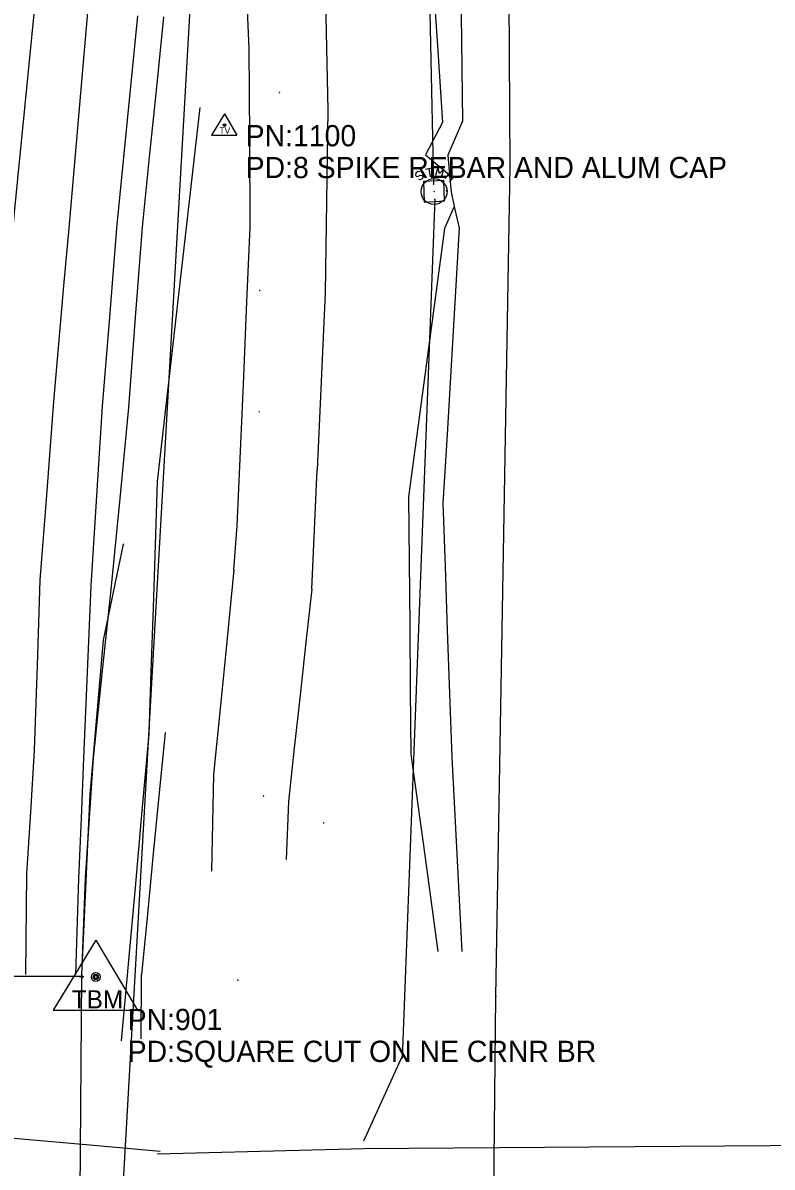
# Model space of a CAD drawing. Extents: x 1930288 to 1941089, y 588389 to 611475.
# Drawn here: x 1930874.5 to 1931050.9, y 598182.1 to 598451.6 of the extents above; entities that cross this region are included whole.
import ezdxf

# ---------------------------------------------------------------- set-up
doc = ezdxf.new("R2010")
doc.units = 0
for name, color, linetype in [('S_BASELINE', 7, 'Continuous'), ('S_BRIDGE', 7, 'Continuous'), ('S_DITCHLINE', 7, 'Continuous'), ('S_DROP_INLET', 7, 'Continuous'), ('S_EDGE_PAVEMENT', 7, 'Continuous'), ('S_GUARDRAIL', 7, 'Continuous'), ('S_MSC_PT_SYM', 7, 'Continuous'), ('S_PAVEMENT_CROWN', 7, 'Continuous'), ('S_PRIMARY_CTL', 7, 'Continuous'), ('S_PRIMARY_CTL_ANNOT', 7, 'Continuous'), ('S_RDW_PT_SYM', 7, 'Continuous'), ('S_SANITARY_SEWER', 7, 'Continuous'), ('S_SECONDARY_CTL', 7, 'Continuous'), ('S_SECONDARY_CTL_ANNOT', 7, 'Continuous'), ('S_SHOULDER', 7, 'Continuous'), ('S_STORM_SEWER', 7, 'Continuous'), ('S_STR_PT_SYM', 7, 'Continuous'), ('S_STREAM', 7, 'Continuous'), ('S_UTL_PT_SYM', 7, 'Continuous')]:
    doc.layers.add(name, color=color, linetype=linetype)

msp = doc.modelspace()

# ---------------------------------------------------------------- linework, layer by layer
at = {"layer": 'S_BASELINE'}
msp.add_line((1930894.27, 598110.49), (1930946.09, 599020.44), dxfattribs=at)
at = {"layer": 'S_BRIDGE'}
for p, q in [((1930888.36, 598226.99), (1930860.72, 598227)), ((1930887.7, 598136.81), (1930888.36, 598226.99))]:
    msp.add_line(p, q, dxfattribs=at)
at = {"layer": 'S_DITCHLINE'}
for points in [[(1930970.71, 598466.55), (1930972, 598447.33), (1930973.28, 598428.1), (1930969.3, 598420.53), (1930974.95, 598415.77), (1930975.3, 598411.84), (1930976.08, 598408.31), (1930973.77, 598403.14), (1930971.65, 598387.34), (1930969.52, 598371.55), (1930967.39, 598355.75), (1930965.27, 598339.95), (1930965.42, 598324.8), (1930965.57, 598309.65), (1930965.72, 598294.5), (1930965.87, 598279.35), (1930969.03, 598256.12), (1930972.19, 598232.9)], [(1930977.56, 598465.96), (1930977.77, 598447.19), (1930977.99, 598428.41), (1930974.55, 598420.45), (1930974.95, 598415.77)], [(1930916.13, 598431.64), (1930913.63, 598409.61), (1930911.14, 598387.59), (1930908.64, 598365.57), (1930906.15, 598343.55), (1930905.65, 598328.67), (1930905.16, 598313.8), (1930904.66, 598298.92), (1930904.17, 598284.05), (1930902.54, 598266), (1930900.92, 598247.96), (1930899.29, 598229.92), (1930897.66, 598211.87)], [(1930976.08, 598408.31), (1930977.25, 598403.25), (1930976.29, 598387.06), (1930975.33, 598370.87), (1930974.37, 598354.68), (1930973.41, 598338.49), (1930973.92, 598323.54), (1930974.43, 598308.59), (1930974.94, 598293.64), (1930975.46, 598278.69), (1930976.64, 598255.8), (1930977.83, 598232.91)], [(1930907.96, 598284.5), (1930906.57, 598270.24), (1930905.19, 598255.98), (1930903.81, 598241.71), (1930902.42, 598227.45)], [(1930902.33, 598212.31), (1930902.42, 598227.45)], [(1930963.83, 598208.28), (1930954.67, 598188.22)]]:
    msp.add_lwpolyline(points, dxfattribs=at)
at = {"layer": 'S_DROP_INLET'}
for points in [[(1930973.58, 598414.44), (1930968.84, 598414.2)], [(1930968.84, 598414.2), (1930969.01, 598409.36), (1930973.8, 598409.66), (1930973.58, 598414.44)]]:
    msp.add_lwpolyline(points, dxfattribs=at)
at = {"layer": 'S_EDGE_PAVEMENT'}
for points in [[(1930925.3, 598627.92), (1930936.56, 598622.51), (1930941.76, 598599.13), (1930942.55, 598578.56), (1930943.33, 598557.99), (1930943.76, 598537.25), (1930944.18, 598516.5), (1930944.75, 598495.82), (1930945.32, 598475.13), (1930945.82, 598453.1), (1930946.32, 598431.07), (1930946.01, 598409.55), (1930945.7, 598388.03), (1930944.74, 598367.17), (1930943.78, 598346.31)], [(1930924.96, 598333.18), (1930925.73, 598350.75), (1930926.49, 598368.33), (1930927.26, 598385.9), (1930928.03, 598403.47), (1930927.92, 598424.51), (1930927.81, 598445.55), (1930926.85, 598467.37), (1930925.9, 598489.18), (1930925.69, 598510.76), (1930925.47, 598532.34), (1930926.46, 598553.81), (1930927.46, 598575.27), (1930926.63, 598597.79), (1930922.74, 598599.04)], [(1930877.33, 598456.1), (1930875.68, 598439.46), (1930874.03, 598422.82), (1930872.39, 598406.18), (1930870.73, 598384.64), (1930869.07, 598363.1), (1930867.63, 598342.37), (1930866.18, 598321.65), (1930865.17, 598301.92), (1930864.16, 598282.2), (1930863.63, 598267.31), (1930863.11, 598252.42), (1930862.8, 598239.89), (1930862.49, 598227.37)], [(1930901.49, 598453.28), (1930899.84, 598436.61), (1930898.18, 598419.94), (1930896.52, 598403.28), (1930894.85, 598382.32), (1930893.18, 598361.36), (1930891.86, 598340.18), (1930890.53, 598319), (1930889.64, 598298.71), (1930888.76, 598278.42), (1930888.18, 598264.26), (1930887.6, 598250.1), (1930886.87, 598227.49)], [(1930942.49, 598318.25), (1930943.13, 598332.28), (1930943.78, 598346.31)], [(1930924.18, 598322.8), (1930924.96, 598333.18)], [(1930924.18, 598322.8), (1930921.77, 598298.69), (1930919.36, 598274.58), (1930918.9, 598251.78)], [(1930942.49, 598318.25), (1930941.13, 598305.75), (1930939.76, 598293.25), (1930938.4, 598280.75), (1930937.03, 598268.24), (1930936.52, 598254.54)]]:
    msp.add_lwpolyline(points, dxfattribs=at)
at = {"layer": 'S_GUARDRAIL'}
for p, q in [((1930893.46, 598306.18), (1930898.15, 598328.8)), ((1930890.3, 598269.99), (1930893.46, 598306.18)), ((1930888.4, 598227.43), (1930890.3, 598269.99))]:
    msp.add_line(p, q, dxfattribs=at)
at = {"layer": 'S_MSC_PT_SYM'}
for points in [[(1930934.89, 598435.22), (1930934.89, 598435.27), (1930934.89, 598435.22), (1930934.84, 598435.22), (1930934.89, 598435.22), (1930934.89, 598435.17), (1930934.89, 598435.22), (1930934.94, 598435.22)], [(1930971.17, 598413.62), (1930971.17, 598413.67), (1930971.17, 598413.62), (1930971.12, 598413.62), (1930971.17, 598413.62), (1930971.17, 598413.57), (1930971.17, 598413.62), (1930971.22, 598413.62)], [(1930974.21, 598412.06), (1930974.21, 598412.11), (1930974.21, 598412.06), (1930974.16, 598412.06), (1930974.21, 598412.06), (1930974.21, 598412.01), (1930974.21, 598412.06), (1930974.26, 598412.06)], [(1930971.47, 598410.05), (1930971.47, 598410.1), (1930971.47, 598410.05), (1930971.42, 598410.05), (1930971.47, 598410.05), (1930971.47, 598410), (1930971.47, 598410.05), (1930971.52, 598410.05)], [(1930930.25, 598388.53), (1930930.25, 598388.58), (1930930.25, 598388.53), (1930930.2, 598388.53), (1930930.25, 598388.53), (1930930.25, 598388.48), (1930930.25, 598388.53), (1930930.3, 598388.53)], [(1930930.16, 598360.03), (1930930.16, 598360.08), (1930930.16, 598360.03), (1930930.11, 598360.03), (1930930.16, 598360.03), (1930930.16, 598359.98), (1930930.16, 598360.03), (1930930.21, 598360.03)], [(1930931.15, 598269.52), (1930931.15, 598269.57), (1930931.15, 598269.52), (1930931.1, 598269.52), (1930931.15, 598269.52), (1930931.15, 598269.47), (1930931.15, 598269.52), (1930931.2, 598269.52)], [(1930945.33, 598263.18), (1930945.33, 598263.23), (1930945.33, 598263.18), (1930945.28, 598263.18), (1930945.33, 598263.18), (1930945.33, 598263.13), (1930945.33, 598263.18), (1930945.38, 598263.18)], [(1930925.1, 598226.15), (1930925.1, 598226.2), (1930925.1, 598226.15), (1930925.05, 598226.15), (1930925.1, 598226.15), (1930925.1, 598226.1), (1930925.1, 598226.15), (1930925.15, 598226.15)], [(1930933.25, 598209.13), (1930933.25, 598209.18), (1930933.25, 598209.13), (1930933.2, 598209.13), (1930933.25, 598209.13), (1930933.25, 598209.08), (1930933.25, 598209.13), (1930933.3, 598209.13)]]:
    msp.add_lwpolyline(points, dxfattribs=at)
at = {"layer": 'S_PAVEMENT_CROWN'}
msp.add_lwpolyline([(1930890.05, 598457.73), (1930888.86, 598444.11), (1930887.67, 598430.49), (1930886.47, 598416.87), (1930885.28, 598403.25), (1930884.09, 598389.63), (1930882.9, 598376.01), (1930881.71, 598362.39), (1930880.11, 598341.36), (1930878.51, 598320.33), (1930877.82, 598300.32), (1930877.13, 598280.3), (1930876.25, 598265.74), (1930875.37, 598251.17), (1930875.13, 598227.51)], dxfattribs=at)
at = {"layer": 'S_PRIMARY_CTL'}
for p, q in [((1930891.66, 598235.59), (1930881.63, 598219.07)), ((1930891.66, 598235.59), (1930901.49, 598219.07)), ((1930881.63, 598219.07), (1930901.49, 598219.07))]:
    msp.add_line(p, q, dxfattribs=at)
for radius in [1.04, 0.609, 0.344]:
    msp.add_circle((1930891.66, 598226.89), radius, dxfattribs=at)
at = {"layer": 'S_RDW_PT_SYM'}
for points in [[(1930898.15, 598328.8), (1930898.15, 598328.85), (1930898.15, 598328.8), (1930898.1, 598328.8), (1930898.15, 598328.8), (1930898.15, 598328.75), (1930898.15, 598328.8), (1930898.2, 598328.8)], [(1930893.46, 598306.18), (1930893.46, 598306.23), (1930893.46, 598306.18), (1930893.41, 598306.18), (1930893.46, 598306.18), (1930893.46, 598306.13), (1930893.46, 598306.18), (1930893.51, 598306.18)], [(1930890.3, 598269.99), (1930890.3, 598270.04), (1930890.3, 598269.99), (1930890.25, 598269.99), (1930890.3, 598269.99), (1930890.3, 598269.94), (1930890.3, 598269.99), (1930890.35, 598269.99)], [(1930888.4, 598227.43), (1930888.4, 598227.48), (1930888.4, 598227.43), (1930888.35, 598227.43), (1930888.4, 598227.43), (1930888.4, 598227.38), (1930888.4, 598227.43), (1930888.45, 598227.43)]]:
    msp.add_lwpolyline(points, dxfattribs=at)
at = {"layer": 'S_SANITARY_SEWER'}
for p, q in [((1930989.23, 598417.74), (1930987.94, 598658.53)), ((1930985.88, 598222.31), (1930989.23, 598417.74)), ((1930984.75, 598112), (1930985.88, 598222.31))]:
    msp.add_line(p, q, dxfattribs=at)
at = {"layer": 'S_SECONDARY_CTL'}
for p, q in [((1930921.95, 598430.14), (1930918.94, 598425.18)), ((1930921.95, 598430.14), (1930924.9, 598425.18)), ((1930918.94, 598425.18), (1930924.9, 598425.18))]:
    msp.add_line(p, q, dxfattribs=at)
for radius in [0.311, 0.183, 0.103]:
    msp.add_circle((1930921.95, 598427.53), radius, dxfattribs=at)
at = {"layer": 'S_SHOULDER'}
msp.add_lwpolyline([(1930907.6, 598452.98), (1930905.93, 598436.47), (1930904.26, 598419.96), (1930902.59, 598403.45), (1930900.97, 598382.21), (1930899.36, 598360.98), (1930897.29, 598339.57), (1930895.22, 598318.15), (1930893.11, 598298.28), (1930891.01, 598278.4), (1930890.09, 598264.33), (1930889.18, 598250.25), (1930888.32, 598227.26)], dxfattribs=at)
at = {"layer": 'S_STORM_SEWER'}
for p, q in [((1930967.6, 598579.05), (1930971.17, 598413.62)), ((1930969.27, 598417.15), (1930970.78, 598417.42)), ((1930966.98, 598416.18), (1930966.9, 598415.79)), ((1930966.9, 598415.79), (1930967.1, 598415.52)), ((1930967.52, 598416.56), (1930966.98, 598416.18)), ((1930967.1, 598415.52), (1930967.52, 598415.4)), ((1930967.95, 598416.49), (1930967.52, 598416.56)), ((1930967.52, 598415.4), (1930968.07, 598415.75)), ((1930968.07, 598414.59), (1930967.68, 598414.67)), ((1930968.07, 598415.75), (1930968.53, 598415.67)), ((1930968.61, 598414.98), (1930968.07, 598414.59)), ((1930968.53, 598415.67), (1930968.69, 598415.4)), ((1930968.69, 598415.4), (1930968.61, 598414.98)), ((1930970.04, 598417.3), (1930970.39, 598415.36)), ((1930973.96, 598414.94), (1930975.2, 598416.41)), ((1930974.61, 598415.71), (1930975.58, 598414.9)), ((1930976.16, 598415.6), (1930974.92, 598414.12)), ((1930971.47, 598410.05), (1930963.76, 598207.83))]:
    msp.add_line(p, q, dxfattribs=at)
msp.add_lwpolyline([(1930973.06, 598415.25), (1930973.61, 598417.11), (1930972.56, 598416.1), (1930972.17, 598417.53), (1930971.63, 598415.67)], dxfattribs=at)
msp.add_circle((1930971.31, 598411.87), 3.05, dxfattribs=at)
at = {"layer": 'S_STR_PT_SYM'}
msp.add_lwpolyline([(1930888.36, 598226.99), (1930888.36, 598227.49), (1930888.36, 598226.99), (1930887.86, 598226.99), (1930888.36, 598226.99), (1930888.36, 598226.49), (1930888.36, 598226.99), (1930888.86, 598226.99)], dxfattribs=at)
at = {"layer": 'S_STREAM'}
for points in [[(1930906.83, 598185.8), (1930890.27, 598187.32), (1930874.15, 598188.74), (1930858.02, 598190.16), (1930839.57, 598191.65), (1930821.12, 598193.14), (1930807.8, 598195.95), (1930794.49, 598198.75), (1930781.17, 598201.56), (1930767.85, 598204.36), (1930754.04, 598206.75), (1930740.24, 598209.13), (1930726.43, 598211.51), (1930712.62, 598213.9), (1930698.26, 598212.92), (1930683.89, 598211.94), (1930669.53, 598210.96), (1930655.17, 598209.99), (1930636.67, 598208.34)], [(1931456.27, 598188.39), (1931358.03, 598189.57), (1931267.44, 598187.22), (1931158.27, 598183.79), (1931061.05, 598187.22), (1930954.79, 598186.44), (1930906.14, 598185.15)]]:
    msp.add_lwpolyline(points, dxfattribs=at)
at = {"layer": 'S_UTL_PT_SYM'}
for points in [[(1930989.23, 598417.74), (1930989.23, 598417.79), (1930989.23, 598417.74), (1930989.18, 598417.74), (1930989.23, 598417.74), (1930989.23, 598417.69), (1930989.23, 598417.74), (1930989.28, 598417.74)], [(1930971.17, 598413.62), (1930971.17, 598413.67), (1930971.17, 598413.62), (1930971.12, 598413.62), (1930971.17, 598413.62), (1930971.17, 598413.57), (1930971.17, 598413.62), (1930971.22, 598413.62)], [(1930971.31, 598411.87), (1930971.31, 598411.92), (1930971.31, 598411.87), (1930971.26, 598411.87), (1930971.31, 598411.87), (1930971.31, 598411.82), (1930971.31, 598411.87), (1930971.36, 598411.87)], [(1930971.47, 598410.05), (1930971.47, 598410.1), (1930971.47, 598410.05), (1930971.42, 598410.05), (1930971.47, 598410.05), (1930971.47, 598410), (1930971.47, 598410.05), (1930971.52, 598410.05)], [(1930985.88, 598222.31), (1930985.88, 598222.36), (1930985.88, 598222.31), (1930985.83, 598222.31), (1930985.88, 598222.31), (1930985.88, 598222.26), (1930985.88, 598222.31), (1930985.93, 598222.31)], [(1930963.76, 598207.83), (1930963.76, 598207.88), (1930963.76, 598207.83), (1930963.71, 598207.83), (1930963.76, 598207.83), (1930963.76, 598207.78), (1930963.76, 598207.83), (1930963.81, 598207.83)]]:
    msp.add_lwpolyline(points, dxfattribs=at)

# ---------------------------------------------------------------- texts
at = {"layer": 'S_PRIMARY_CTL'}
msp.add_text('TBM', height=4.287, rotation=360, dxfattribs=at).set_placement((1930886.01, 598219.5))
at = {"layer": 'S_PRIMARY_CTL_ANNOT'}
for s, p in [('PN:901', (1930899.16, 598214.39)), ('PD:SQUARE CUT ON NE CRNR BR', (1930899.16, 598206.89))]:
    msp.add_text(s, height=5, dxfattribs=at).set_placement(p)
at = {"layer": 'S_SECONDARY_CTL'}
msp.add_text('TV', height=1.5, rotation=360, dxfattribs=at).set_placement((1930920.75, 598425.52))
at = {"layer": 'S_SECONDARY_CTL_ANNOT'}
for s, p in [('PN:1100', (1930926.95, 598422.53)), ('PD:8 SPIKE REBAR AND ALUM CAP', (1930926.95, 598415.03))]:
    msp.add_text(s, height=5, dxfattribs=at).set_placement(p)

doc.saveas('drawing.dxf')
